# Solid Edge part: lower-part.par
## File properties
Author: Deepak Maini
Template: Part8.par
Last saved by: MYPC
Revision: 6
Application: Solid Edge
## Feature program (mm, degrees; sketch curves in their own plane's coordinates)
body "unnamed Body 1"
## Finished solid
Body 1: solid body, 47 faces, 113 edges, 68 vertices.
  Faces by surface: plane 32, torus 8, cylinder 6, cone 1
  Edges by curve: circle 49, line 49, intersection 15
Bounding box of the edges (mm; curved faces can reach further): 68.011 x 85.812 x 6.000, from (-34.0057, -34, -6) to (34.0057, 51.8118, 0).
Cylindrical faces by radius (mm): R2.5 x2, R3 x1, R4.5 x2, R8 x1
Conical faces (half-angle, radius in mm at the cone's reference point): 45 deg R8 x1
Toroidal faces (ring radius, tube radius in mm): R18 r4 x1, R18 r6 x1, R28 r4 x1, R28 r6 x1, R60.4976 r4 x2, R60.4976 r6 x2
Planar faces by outward normal: +x 5, +y 4, +z 11, -x 4, -y 5, -z 3
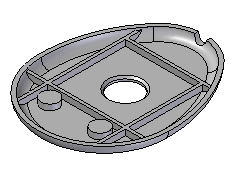
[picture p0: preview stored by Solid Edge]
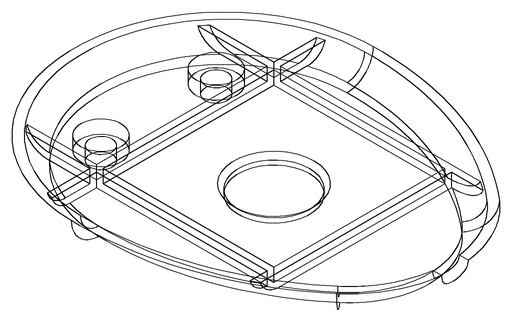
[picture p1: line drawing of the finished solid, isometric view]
